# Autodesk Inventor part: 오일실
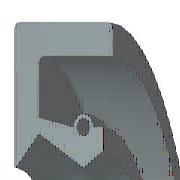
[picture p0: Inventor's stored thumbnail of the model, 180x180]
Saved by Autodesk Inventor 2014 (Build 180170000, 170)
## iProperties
Created: 2009-02
Part Number: 오일실
Material: 고무
Description: 오일-실
Document SubType Name: Modeling
Standard: KS B 2804
Designer: SeoGD™
Standards Organization: KS
Language: ko-KR
Size Designation: D - 10 20 7
Categories: <MemberInstance><Categories><Category DisplayName="샤프트 부품" InternalName="7f7aeb1f-a693-4053-b835-cee3144e0d98" Mnemonic="SHFT"><Category DisplayName="실링" Intern
Density: 0.93 g/cm^3
Appearance: 고무 - 검은색 - 버전 1.1
Mass: 1.11329 g
Surface Area: 16.3871 cm^2
Volume: 1.19708 cm^3
IsCustomPart: 0
Author: SeoGD™
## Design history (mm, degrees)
revolve "본체" stored, may be unused: angle "d17" = 90 deg
revolve "스프링1" stored, may be unused: angle "d18" = 90 deg
body "Solid1"
sketch "스케치1"
  geometry: L1 (0, 10)-(7, 10); L2 (7, 8.25)-(1.75, 8.25); L3 (1.75, 6.75)-(4.9, 5); L4 (4.9, 5)-(0, 5); L5 (0, 0)-(9.586, 0) reference; L6 (4.9, 5)-(6.3, 5.875); L7 (0, 18)-(0, -3) reference; L8 (-1.941, 0)-(11.507, 0) reference; L9 (4.2, 7.1)-(1.75, 7.59); L10 (1.75, 7.59)-(1.75, 8.25); L11 (0, 10)-(0, 5.088); L12 (4.9, 5)-(0, 5); L13 (1.75, 6.75)-(0.152, 5.028); L14 (7, 10)-(7, 8.25); L15 (5.6, 7.1)-(6.3, 7.1); L16 (6.3, 7.1)-(6.3, 5.875); C1 r 0.455 at (4.9, 7.1); A1 r 0.7 centre (4.9, 7.1) between (5.6, 7.1) and (4.2, 7.1); A2 r 0.088 centre (0.088, 5.088) between (0, 5.088) and (0.152, 5.028); 1 further point
  constraints: 28 end point, 5 horizontal alignment, 5 point on line, 4 point on circle, 4 vertical alignment, 3 centre point, 3 tangent, 2 collinear, 2 horizontal, 2 perpendicular, 1 coincident, 1 parallel
  dimensions: "d0" = 20 diameter of L1 L5 (= SD2); "d1" = 1.75 distance of L1.end L2.start (= SD); "d2" = 0.91 diameter of C1 (= SPDI); "d3" = 1.4 diameter of A1 (= SPDA); "d4" = 10 diameter of L3.end L5 (= NND); "d5" = 13.5 diameter of L3.start L5 (= TKDM); "d7" = 15.18 diameter of L9.end L5 (= TKDM + 0.24 x SWDT); "d8" = 1.75 distance between parallel lines of L11 L10 (= SD); "d9" = 4.9 distance from line of L11 C1.centre (= SPDST); "d10" = 14.2 diameter of C1.centre L5 (= HLDM); "d11" = 0.0875 radius of A2 (= 0.25 x LAB); "d12" = 6.3 distance between parallel lines of L11 L16 (= SDI); "d13" = 11.75 diameter of L6.end L5 (= ABDM); "d14" = 7 distance from line of L11 L1.end (= SWDT)
fillet "모깎기1" dims "d6" = 0.3 (= RR)
other parameters: "SD2" = 20 [user parameter; used in 1 equation term], "SWDT" = 7 [user parameter; used in 2 equation terms], "RR" = 0.3 [user parameter; used in 1 equation term], "SD" = 1.75 [user parameter; used in 2 equation terms], "NND" = 10 [user parameter; used in 1 equation term], "SPDA" = 1.4 [user parameter; used in 1 equation term], "SPDI" = 0.91 [user parameter; used in 1 equation term], "TKDM" = 13.5 [user parameter; used in 2 equation terms], "HLDM" = 14.2 [user parameter; used in 1 equation term], "ABDM" = 11.75 [user parameter; used in 1 equation term], "SDI" = 6.3 [user parameter; used in 1 equation term], "SPDST" = 4.9 [user parameter; used in 1 equation term], "LAB" = 0.35 [user parameter; used in 1 equation term], "d15" = 0, "d16" = 0, "d19" = 0
